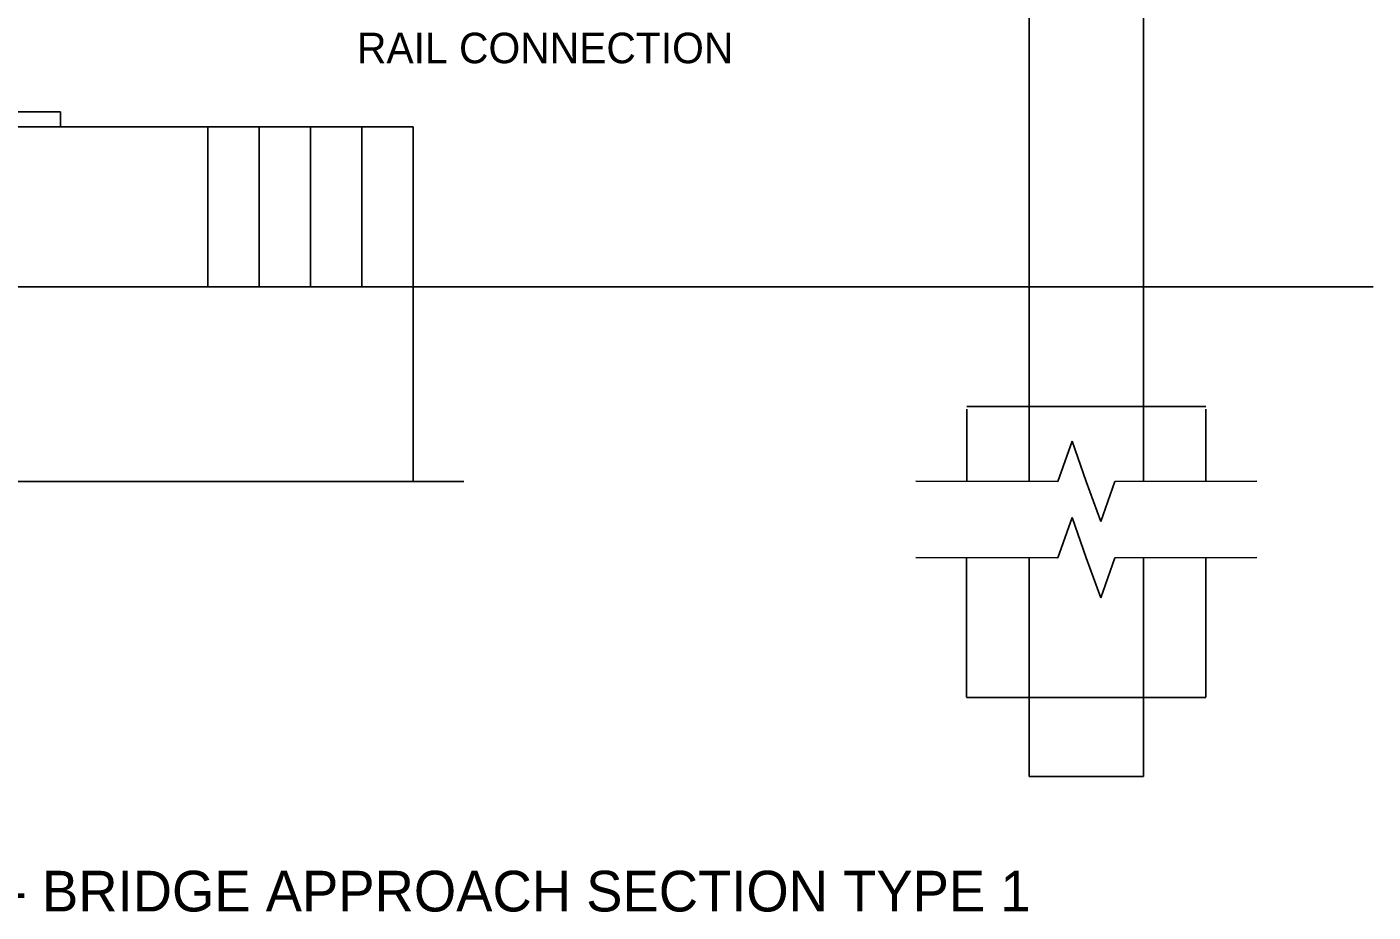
# Model space of a CAD drawing. Extents: x 49991.4 to 50021, y 49987.6 to 50011.4.
# Drawn here: x 50001.527 to 50004.174, y 49991.326 to 49993.066 of the extents above; entities that cross this region are included whole.
import ezdxf

# ---------------------------------------------------------------- set-up
doc = ezdxf.new("R2010")
doc.units = 0
for name, color, linetype in [('Level 1', 7, 'Continuous'), ('Level 2', 7, 'Continuous'), ('Level 4', 7, 'Continuous'), ('Level 6', 7, 'Continuous')]:
    doc.layers.add(name, color=color, linetype=linetype)

msp = doc.modelspace()

# ---------------------------------------------------------------- linework, layer by layer
at = {"layer": 'Level 1'}
for p, q in [((50003.4976, 49992.5551), (50003.4976, 49993.3264)), ((50003.7222, 49992.5551), (50003.7222, 49993.3264)), ((50000.8645, 49992.8993), (50001.5926, 49992.8993)), ((50001.5926, 49992.8992), (50001.5926, 49992.8695)), ((50002.2862, 49992.8695), (50000.5498, 49992.8695)), ((50001.8823, 49992.5551), (50001.8823, 49992.8695)), ((50001.9833, 49992.5551), (50001.9833, 49992.8695)), ((50002.0843, 49992.5551), (50002.0843, 49992.8695)), ((50002.1853, 49992.5551), (50002.1853, 49992.8695)), ((50002.2862, 49992.5551), (50002.2862, 49992.8695)), ((50002.0942, 49992.555), (50000.5502, 49992.555)), ((50002.0942, 49992.5551), (50004.1738, 49992.5551))]:
    msp.add_line(p, q, dxfattribs=at)
at = {"layer": 'Level 4'}
for p, q in [((50002.2862, 49992.1726), (50002.2862, 49992.5551)), ((50003.4976, 49992.5551), (50003.4976, 49992.1732)), ((50003.7222, 49992.5551), (50003.7222, 49992.1732)), ((50003.4976, 49992.3202), (50003.3747, 49992.3202)), ((50003.3747, 49992.1732), (50003.3747, 49992.3145)), ((50003.4976, 49992.3202), (50003.722, 49992.3202)), ((50003.845, 49992.3202), (50003.722, 49992.3202)), ((50003.845, 49992.3202), (50003.845, 49992.3202)), ((50003.845, 49992.1732), (50003.845, 49992.3145)), ((50003.3746, 49991.7485), (50003.3746, 49992.0232)), ((50003.4976, 49991.5931), (50003.4976, 49992.0232)), ((50003.7221, 49991.5931), (50003.7221, 49992.0232)), ((50003.8451, 49991.7485), (50003.8451, 49992.023)), ((50003.8451, 49991.7483), (50003.3746, 49991.7483)), ((50003.4976, 49991.5931), (50003.7221, 49991.5931))]:
    msp.add_line(p, q, dxfattribs=at)
at = {"layer": 'Level 6'}
for p, q in [((50003.5821, 49992.2519), (50003.5542, 49992.1728)), ((50003.5821, 49992.2519), (50003.6099, 49992.1728)), ((50001.485, 49992.1726), (50002.3862, 49992.1726)), ((50003.2747, 49992.1734), (50003.5542, 49992.1728)), ((50003.6099, 49992.1728), (50003.6382, 49992.0938)), ((50003.6661, 49992.1728), (50003.6382, 49992.0938)), ((50003.6661, 49992.1727), (50003.945, 49992.1734)), ((50003.5821, 49992.1019), (50003.5542, 49992.0228)), ((50003.5821, 49992.1019), (50003.6099, 49992.0228)), ((50003.2746, 49992.0234), (50003.5542, 49992.0228)), ((50003.6099, 49992.0228), (50003.6382, 49991.9438)), ((50003.6661, 49992.0228), (50003.6382, 49991.9438)), ((50003.666, 49992.0228), (50003.9451, 49992.0234))]:
    msp.add_line(p, q, dxfattribs=at)

# ---------------------------------------------------------------- texts
at = {"layer": 'Level 2'}
for s, height, p in [('RAIL CONNECTION', 0.06, (50002.1758, 49992.9946)), ('BOX BEAM - BRIDGE APPROACH SECTION TYPE 1', 0.08, (50000.9026, 49991.3275))]:
    msp.add_text(s, height=height, dxfattribs=at).set_placement(p)

doc.saveas('drawing.dxf')
